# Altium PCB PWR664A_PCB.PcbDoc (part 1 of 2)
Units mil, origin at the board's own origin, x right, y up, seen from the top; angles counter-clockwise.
Board outline 3000 x 3000 mil, 4 copper layers (Top Layer, MidLayer1, MidLayer2, Bottom Layer), stack 31 mil thick; 122 components, 46 nets, 275 pads, 124 vias.
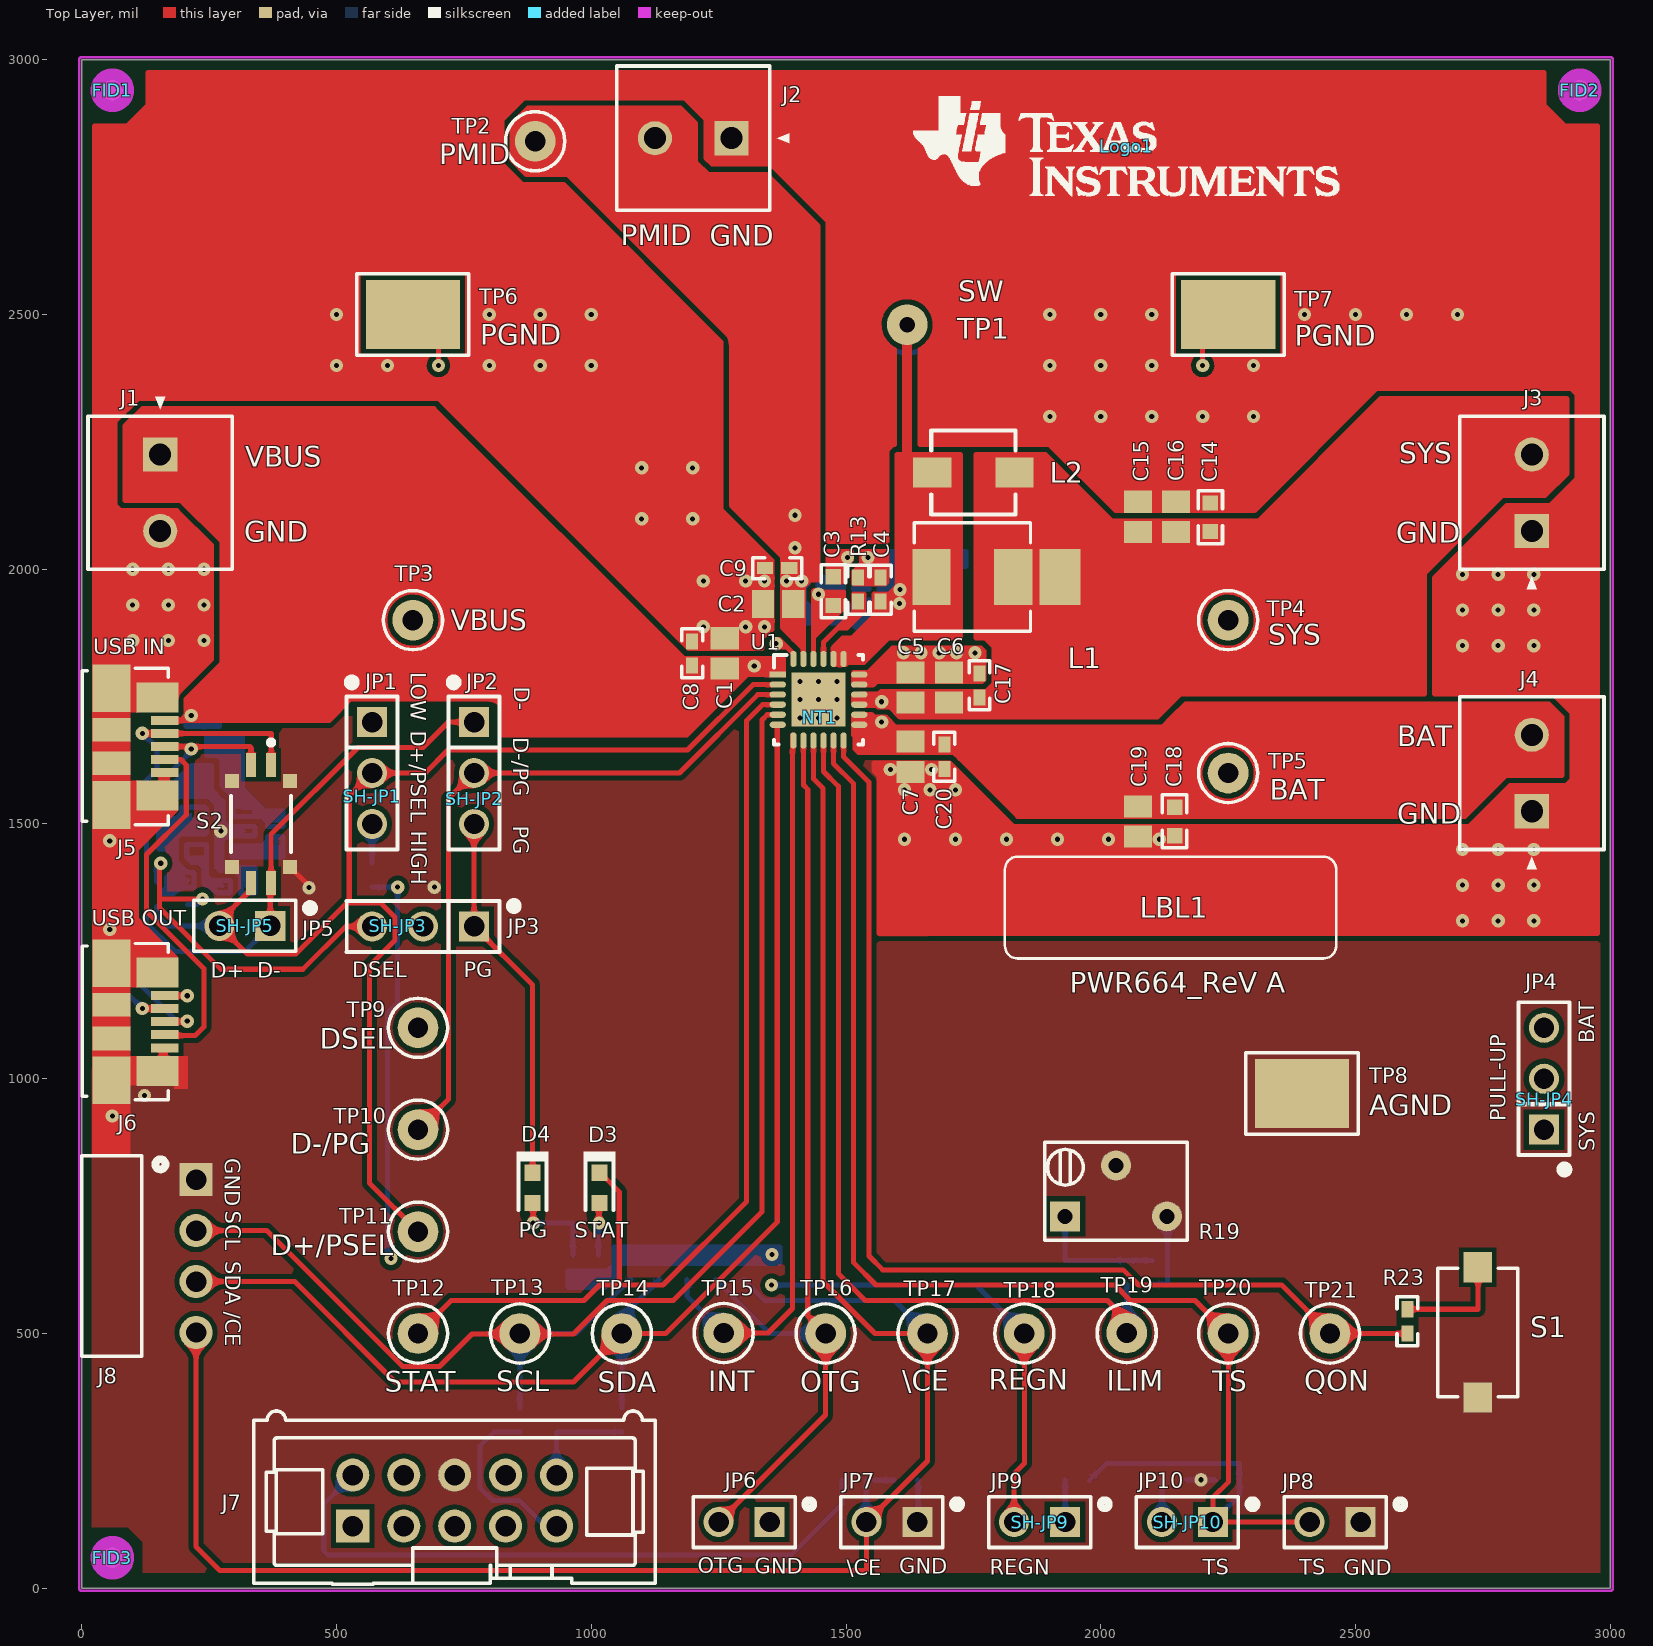
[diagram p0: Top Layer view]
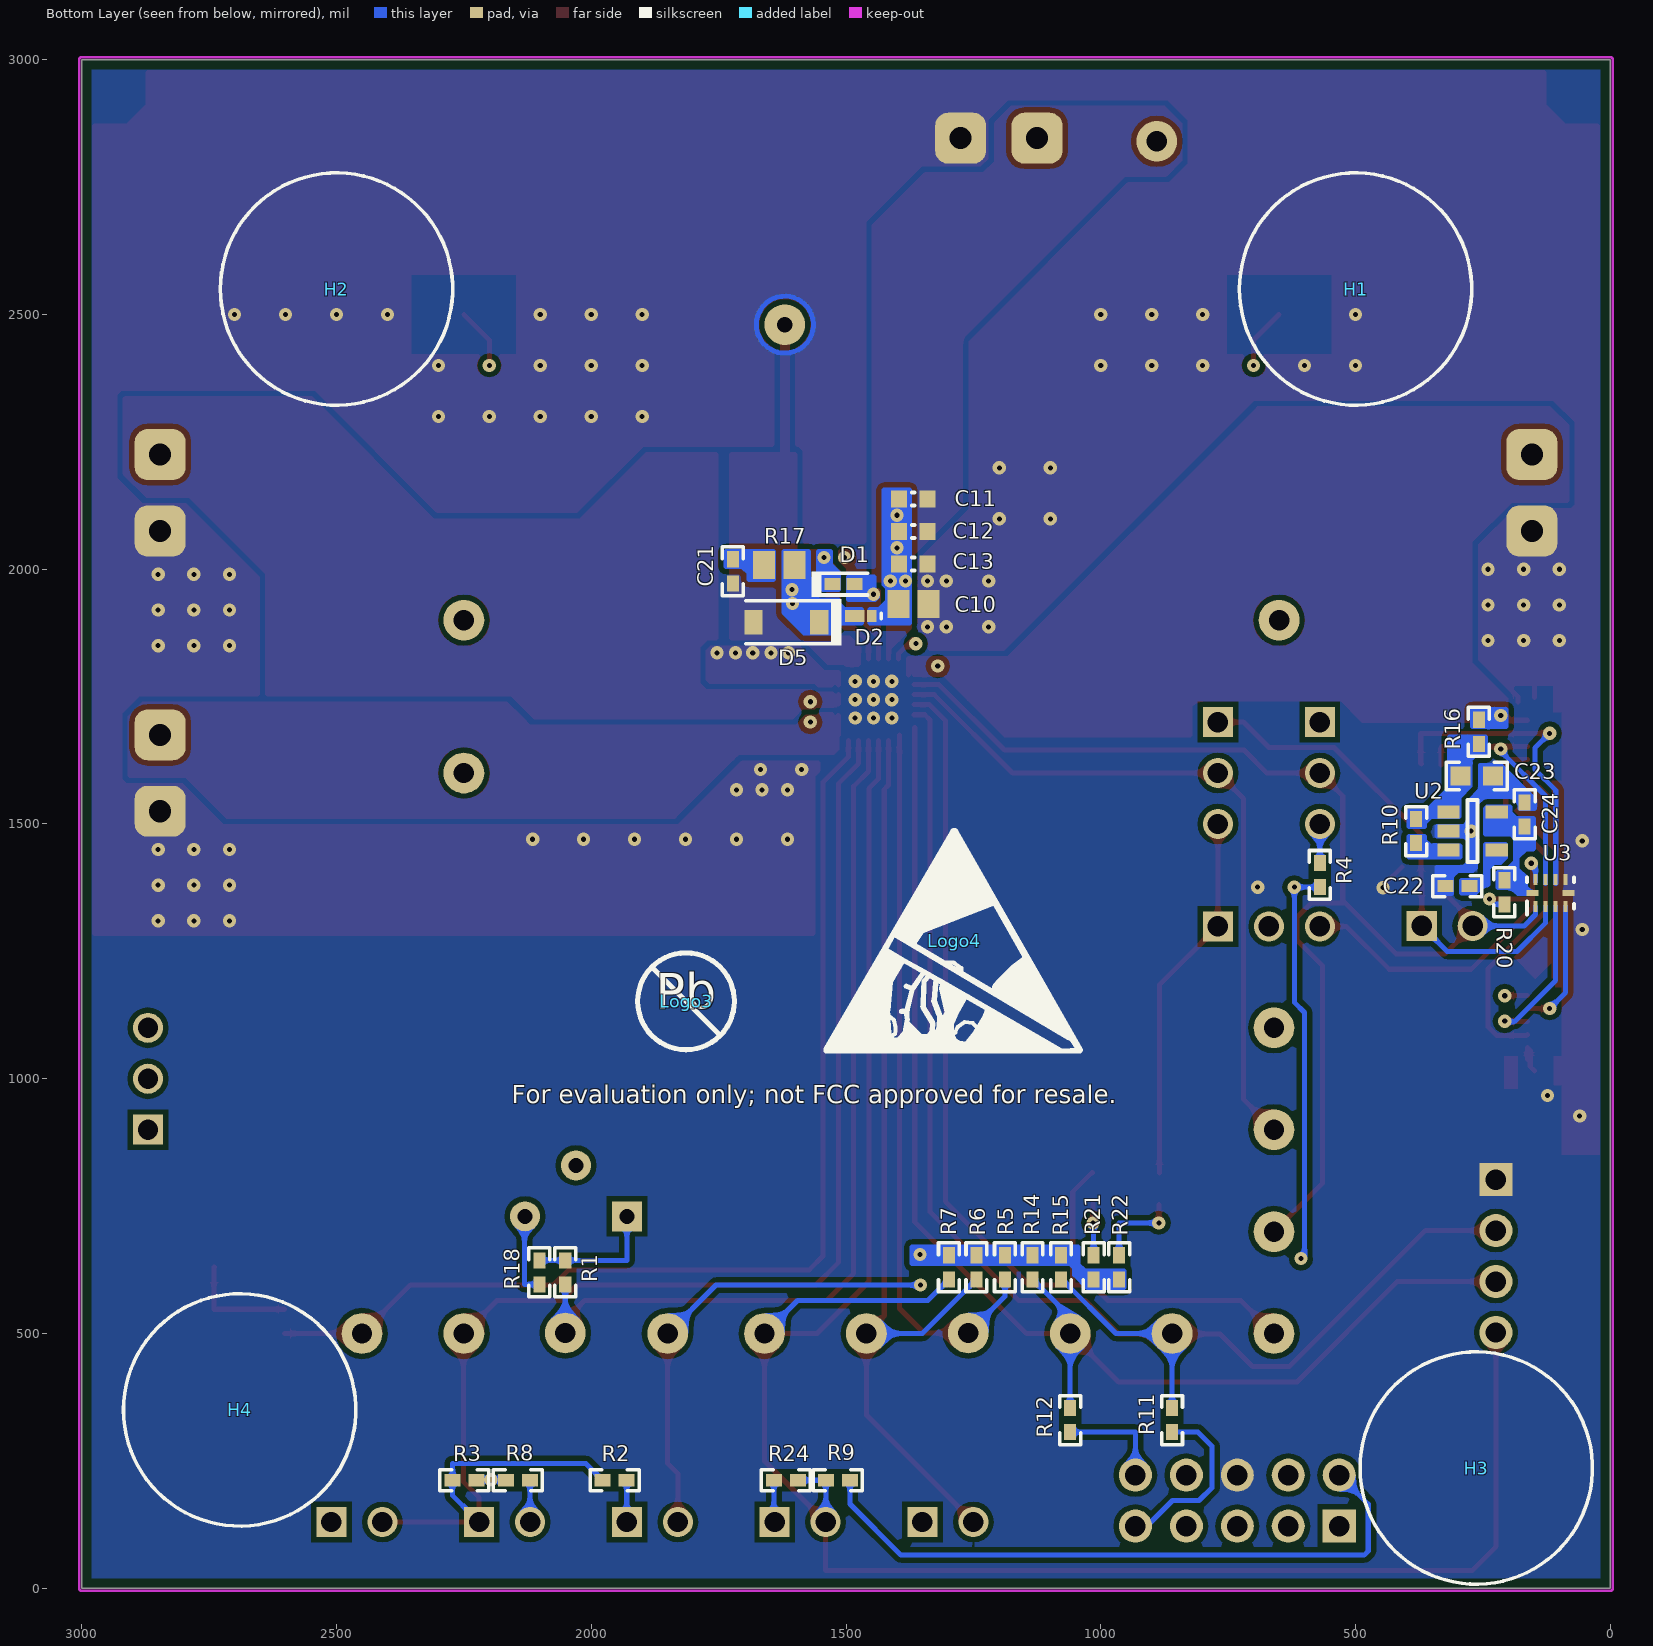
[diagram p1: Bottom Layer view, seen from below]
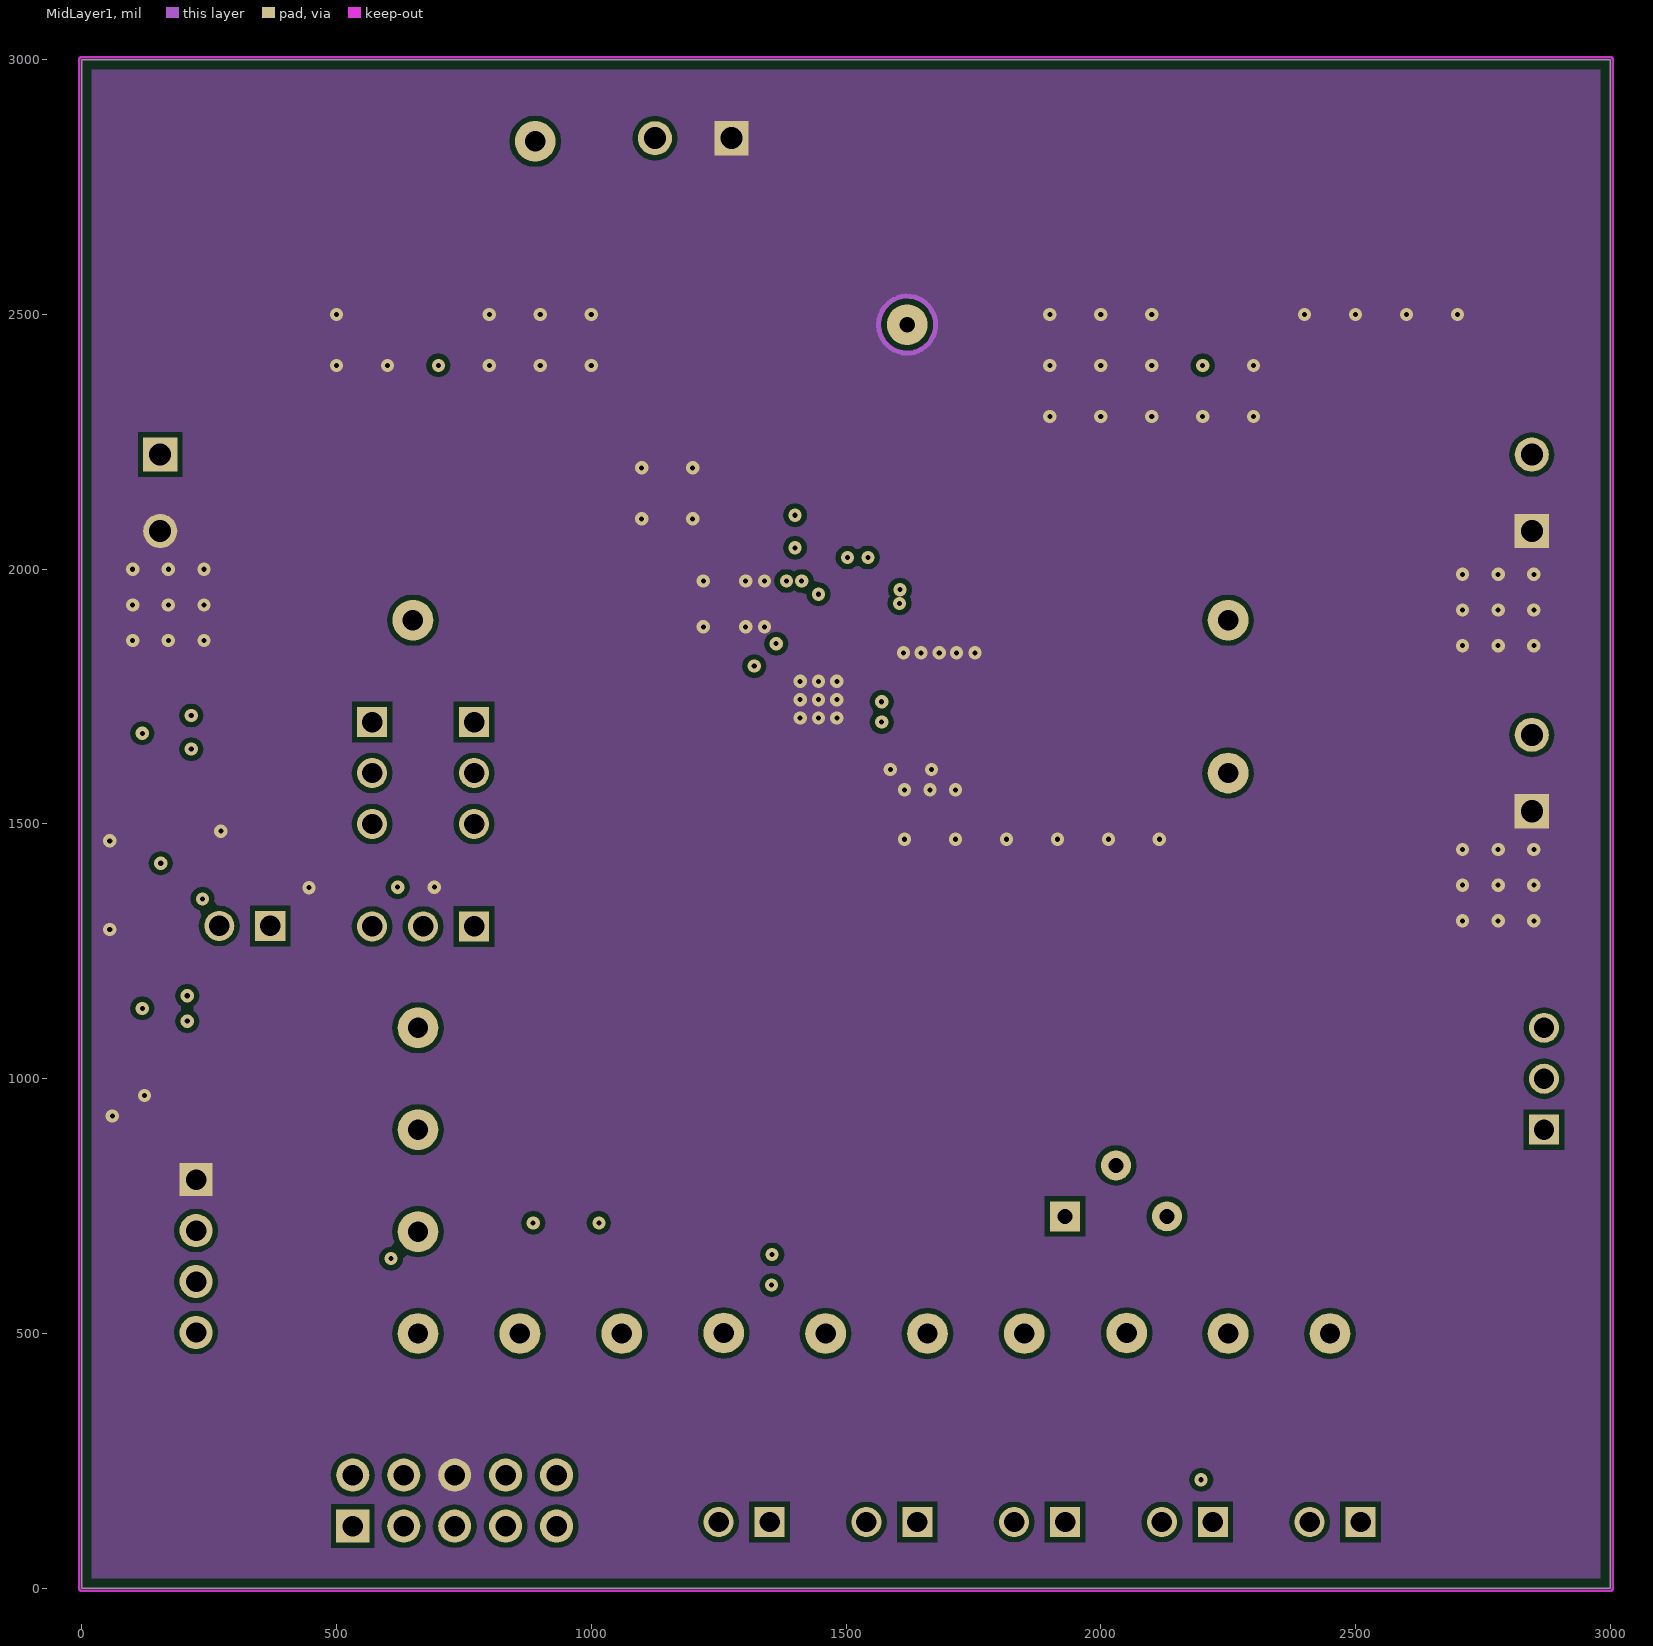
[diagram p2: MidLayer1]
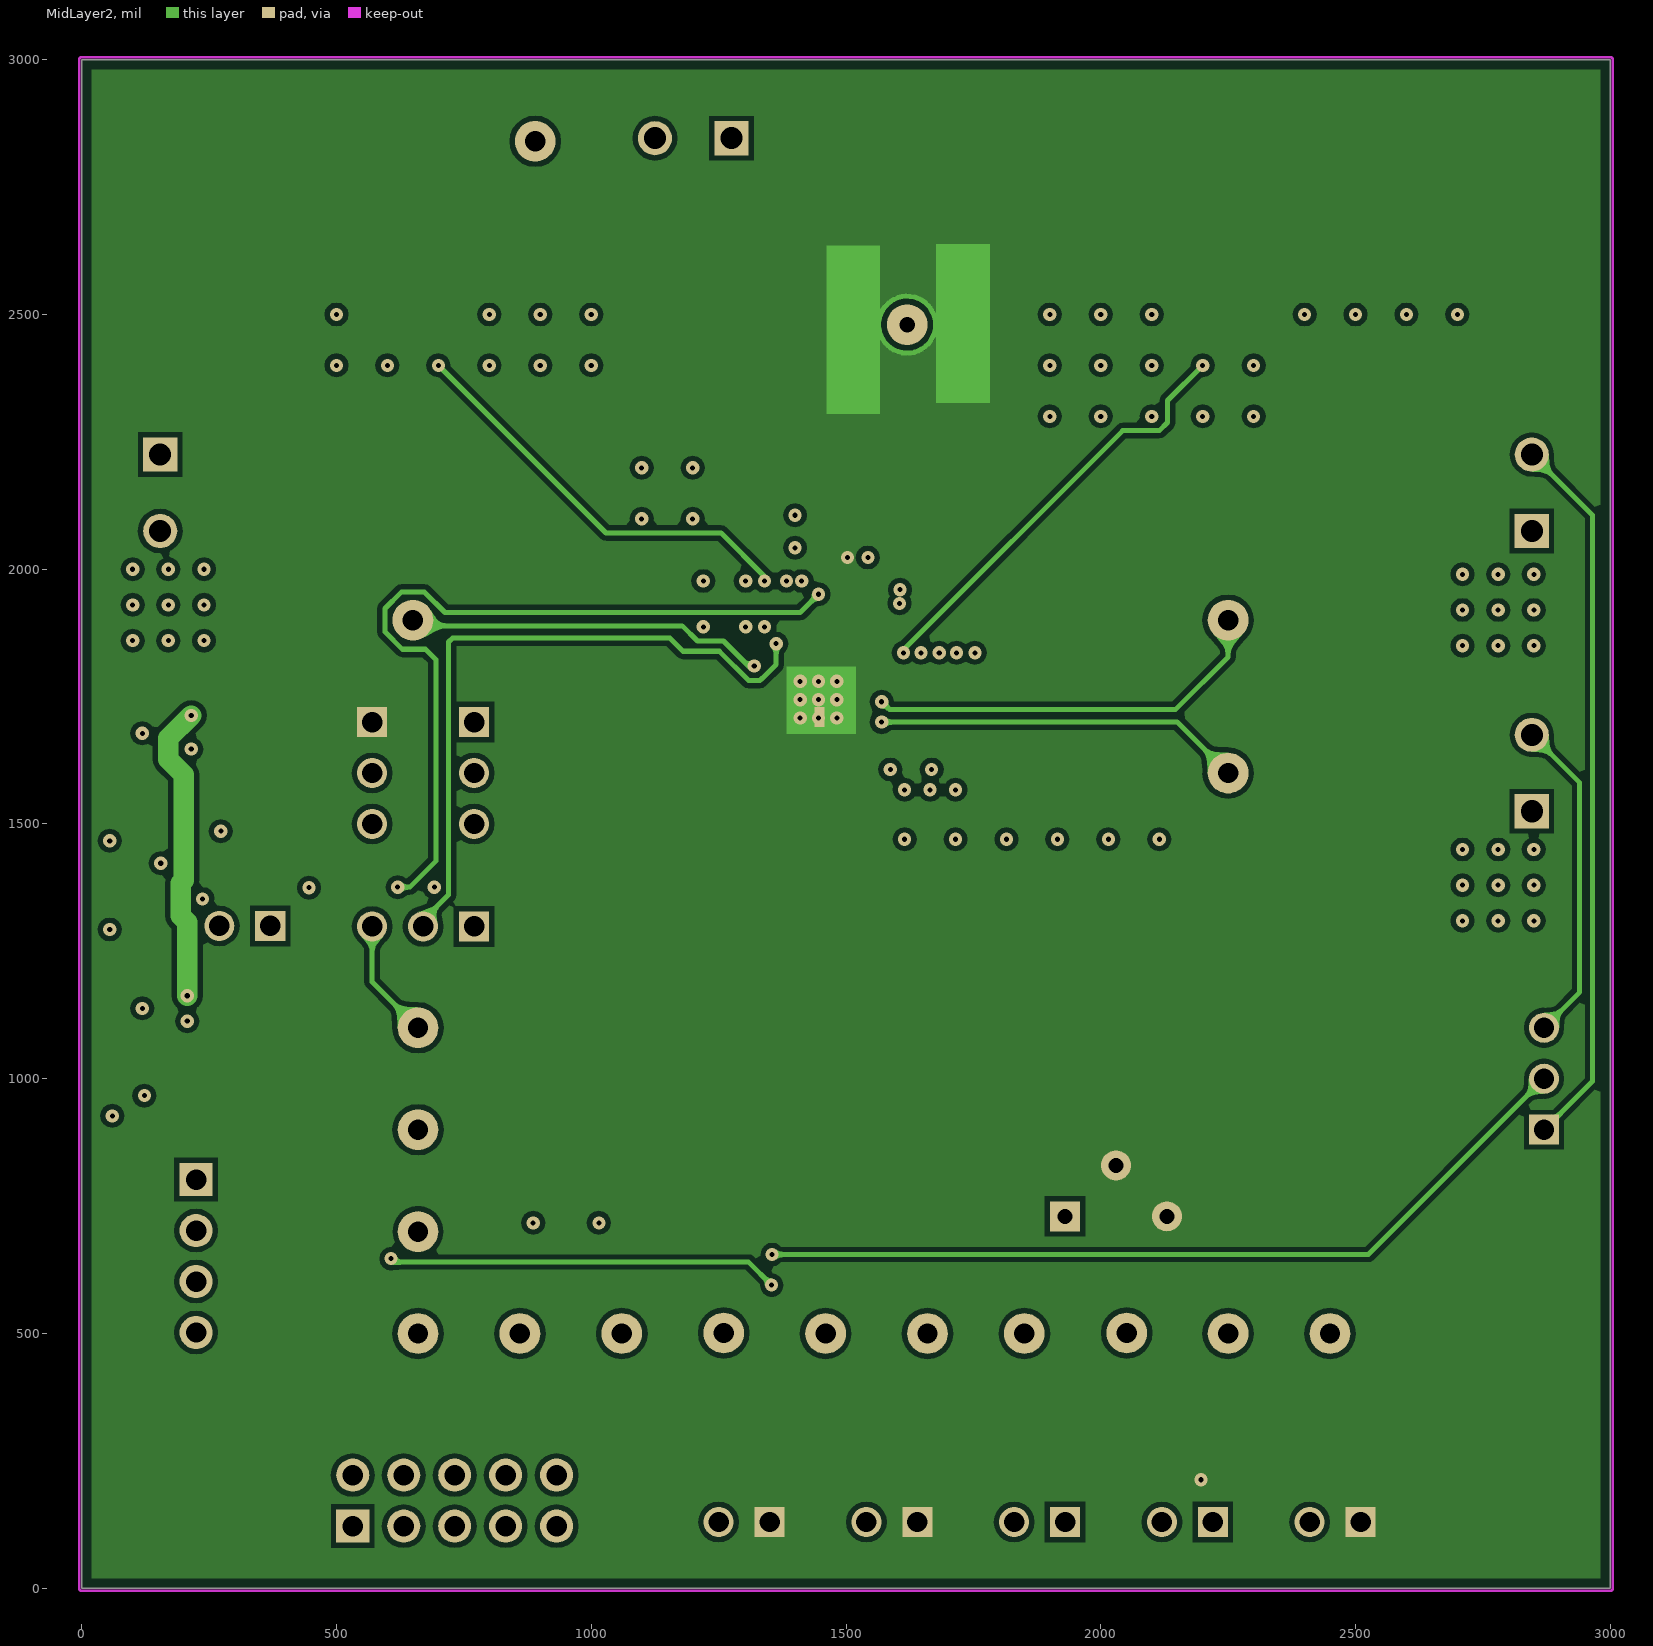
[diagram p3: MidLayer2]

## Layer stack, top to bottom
Top Solder: solder mask 0.4, Solder Resist, Dk 3.5
Top Layer: signal copper 2.8
Dielectric1: core 6.6, FR-4, Dk 4.8
MidLayer1: signal copper 2.8
Dielectric2: prepreg 6.6, FR-4, Dk 4.8
MidLayer2: signal copper 2.8
Dielectric3: core 6.6, FR-4, Dk 4.8
Bottom Layer: signal copper 2.8
Bottom Solder: solder mask 0.4, Solder Resist, Dk 3.5

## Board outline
0,0 3000,0 3000,3000 0,3000 0,0

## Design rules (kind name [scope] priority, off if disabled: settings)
AcuteAngle [All] p1: minimum=4.50000000000000E+0001 checktracksonly=FALSE
AssemblyTestPointUsage [All] p1: valid=2
Clearance Clearance_BoardEdge_MountingHoles [OnCopper and InComponentClass('Mounting Holes') vs IsKeepOut] p1: gap=10
Clearance Clearance_BoardEdge_Poly [OnCopper and InPoly vs IsKeepOut] p2: gap=10
Clearance Clearance_BoardEdge [OnCopper and Not InComponentClass('Logo') and not InComponentClass('FiducialMark') and not InRegion(1000,500,4000,800) and Not IsKeepout vs IsKeepOut] p3: gap=10
Clearance Clearance_Poly [InPolygon] p4: gap=10
Clearance [All] p5: gap=6
ComponentClearance ComponentClearance_Shunt [InComponentClass('Header') vs InComponentClass('Shunt')] p1: gap=10 collisioncheckmode=3 verticalgap=10 showdistances=FALSE
ComponentClearance ComponentClearance_Logo [InComponentClass('Logo')] p2: gap=10 collisioncheckmode=3 verticalgap=10 showdistances=FALSE
ComponentClearance ComponentClearance_ScrewToNut [(HasFootprint('NY PMS 440 0025 PH')) vs (HasFootprint('Keystone_1902C'))] p3: gap=10 collisioncheckmode=3 verticalgap=10 showdistances=FALSE
ComponentClearance ComponentClearance_MountingHoles [InComponentClass('Mounting Holes')] p4: gap=10 collisioncheckmode=3 verticalgap=100000 showdistances=FALSE
ComponentClearance ComponentClearance_SmallPassives [HasFootprint('0201*') or HasFootprint('0402*') or HasFootprint('0508') or HasFootprint('0603*') or HasFootprint('0612') or HasFootprint('0805*') or HasFootprint('0815*') or HasFootprint('0830*') or HasFootprint('1206*') or HasFootprint('1210*') or HasFootprint('1808*') or HasFootprint('1812*') or HasFootprint('1825*') or HasFootprint('2010*') or HasFootprint('2220*') or HasFootprint('2225*') or HasFootprint('2512*') or HasFootprint('2728*') or HasFootprint('3518*') vs HasFootprint('0201*') or HasFootprint('0402*') or HasFootprint('0508') or HasFootprint('0603*') or HasFootprint('0612') or HasFootprint('0805*') or HasFootprint('0815*') or HasFootprint('0830*') or HasFootprint('1206*') or HasFootprint('1210*') or HasFootprint('1808*') or HasFootprint('1812*') or HasFootprint('1825*') or HasFootprint('2010*') or HasFootprint('2220*') or HasFootprint('2225*') or HasFootprint('2512*') or HasFootprint('2728*') or HasFootprint('3518*')] p5: gap=10 collisioncheckmode=3 verticalgap=10 showdistances=FALSE
ComponentClearance ComponentClearance_THtoSMT [IsThruComponent vs IsSMTComponent] p6: gap=10 collisioncheckmode=3 verticalgap=10 showdistances=FALSE
ComponentClearance ComponentClearance_THtoTH [IsThruComponent vs IsThruComponent] p7: gap=10 collisioncheckmode=3 verticalgap=10 showdistances=FALSE
ComponentClearance [All] p8: gap=0 collisioncheckmode=3 verticalgap=0 showdistances=FALSE
DiffPairsRouting [All] p1: maxlimit=100 minlimit=10 mostfreqgap=10 toplayer_minwidth=15 toplayer_maxwidth=15 toplayer_prefwidth=15 midlayer1_minwidth=15 midlayer1_maxwidth=15 midlayer1_prefwidth=15 midlayer2_minwidth=15 midlayer2_maxwidth=15 midlayer2_prefwidth=15 bottomlayer_minwidth=15 bottomlayer_maxwidth=15 bottomlayer_prefwidth=15 maxuncoupledlength=1000
FabricationTestPointUsage TestPointUsage [All] p1: valid=2 allowmultiple=FALSE
FabricationTestpoint Testpoint [All] p1: side=3 testpointundercomponent=TRUE minsize=40 maxsize=100 preferedsize=60 minholesize=0 maxholesize=40 preferedholesize=32 testpointgrid=1 allowsidetop=TRUE allowsidebottom=TRUE usegrid=TRUE gridtolerance=0.01
FanoutControl Fanout_LCC [IsLCC] p1: bgadir=Out bgaviamode=Centered fanoutstyle=Auto fanoutdirection=Alternating viagrid=1 // Fanout_LCC (Default Rule)
FanoutControl Fanout_BGA [IsBGA] p2: bgadir=Out bgaviamode=Centered fanoutstyle=Auto fanoutdirection=Alternating viagrid=1 // Fanout_BGA (Default Rule)
FanoutControl Fanout_Default [All] p4: bgadir=Out bgaviamode=Centered fanoutstyle=Auto fanoutdirection=Alternating viagrid=1 // Fanout_Default (Default Rule)
FanoutControl Fanout_Small [(CompPinCount < 5)] p5: bgadir=Out bgaviamode=Centered fanoutstyle=Auto fanoutdirection=OutThenIn viagrid=1 // Fanout_Small (Default Rule)
HoleSize [All] p1: absolutevalues=TRUE maxlimit=500 minlimit=8 maxpercent=80.000 minpercent=20.000
MinimumAnnularRing MinimumAnnularRing_ThermalPadVias [IsVia and InAnyComponent] p1: minimumring=4
MinimumAnnularRing [All] p2: minimumring=6
MinimumSolderMaskSliver MinimumSolderMaskSliver_Logo [InComponentClass('Logo') vs InComponentClass('Logo')] p1: minsoldermaskwidth=0.7
MinimumSolderMaskSliver [All] p2: minsoldermaskwidth=3.94
PlaneClearance [All] p1: clearance=10
PlaneConnect [All] p1: planeconnectstyle=NoConnect reliefexpansion=10 reliefentries=4 reliefconductorwidth=10 reliefairgap=10
PolygonConnect [All] p1: connectstyle=Direct reliefconductorwidth=10 reliefentries=4 polygonreliefangle="90 Angle" airgapwidth=10
RoutingCorners [All] p1: cornerstyle=45-Degree minsetback=10 maxsetback=100
RoutingVias ThermalPadVias [IsVia and InAnyComponent] p1: holewidth=10 width=26 viastyle="Through Hole" minholewidth=6 minwidth=20 maxholewidth=100 maxwidth=200
RoutingVias [All] p2: holewidth=10 width=26 viastyle="Through Hole" minholewidth=6 minwidth=8 maxholewidth=200 maxwidth=300
SMDToCorner [All] p1: distance=0
SilkToSilkClearance [All] p1: silktosilkclearance=3
SilkToSolderMaskClearance SilkscreenOverComponentPads [IsPad] p1: minsilkscreentomaskgap=3 clearancetoexposedcopper=TRUE
SolderMaskExpansion [All] p1: expansion=0
UnpouredPolygon [All] p1: allowunpoured=FALSE
Width [All] p1: maxlimit=100 minlimit=5 preferedwidth=10 checkconnectedcopper=TRUE
13 further rules are at their usual default settings.

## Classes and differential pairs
component class Label: LBL1
component class FiducialMark: FID1 FID2 FID3
component class PWR664RevA_Hardware_ANSI-B: FID1 FID2 FID3 H1 H2 H3 H4 LBL1 Logo1 Logo2 Logo3 Logo4 SH-JP1 SH-JP2 SH-JP3 SH-JP4 SH-JP5 SH-JP9 SH-JP10 ZZ1 ZZ2 ZZ3 ZZ4
component class Logo: Logo1
component class PWR664RevA_Schematic: C1 C2 C3 C4 C5 C6 C7 C8 C9 C10 C11 C12 C13 C14 C15 C16 C17 C18 C19 C20 C21 C22 C23 C24 D1 D2 D3 D4 D5 J1 J2 J3 J4 J5 J6 J7 J8 JP1 JP2 JP3 JP4 JP5 JP6 JP7 JP8 JP9 JP10 L1 L2 NT1 R1 R2 R3 R4 R5 R6 R7 R8 R9 R10 R11 R12 R13 R14 R15 R16 R17 R18 R19 R20 R21 R22 R23 R24 S1 S2 TP2 TP3 TP4 TP5 TP6 TP7 TP8 TP9 TP10 TP11 TP12 TP13 TP14 TP15 TP16 TP17 TP18 TP19 TP20 TP21 U1 U2 U3
component class AssemblyNote: ZZ1 ZZ2 ZZ3 ZZ4
component class Shunt: SH-JP1 SH-JP2 SH-JP3 SH-JP4 SH-JP5 SH-JP9 SH-JP10

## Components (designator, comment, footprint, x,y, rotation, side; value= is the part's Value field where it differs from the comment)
C1 "GRM219R71E105KA88D" 0805L 1262,1835 r90 top
C2 "C2012X5R1E106K125AB" 0805L 1367,1932 r180 top
C3 "GRM188R61C475KAAJ" 0603_HV 1475,1957 r270 top
C4 "GRM155R71E473KA88D" 0402 1568,1960 r90 top
C5 "GRM21BR71A106KE51L" 0805L 1627,1768 r90 top
C6 "GRM21BR71A106KE51L" 0805L 1702,1768 r90 top
C7 "GRM21BR71A106KE51L" 0805L 1627,1632 r270 top
C8 "C1005C0G1E102J" 0402 1198,1835 r90 top
C9 "C1005C0G1E102J" 0402 1365,2002 r180 top
C10 "GRM21BR61E226ME44" 0805L 1367.5,1932 r180 bottom
C11 "GRM188R61E106MA73" 0603L 1368,2138 r180 bottom
C12 "GRM188R61E106MA73" 0603L 1368,2010 r180 bottom
C13 "GRM188R61E106MA73" 0603L 1368,2074 r180 bottom
C14 "C1608X7R1C104K" 0603_HV 2215,2102 r90 top
C15 "GRM21BR71A106KE51L" 0805L 2073,2103 r90 top
C16 "GRM21BR71A106KE51L" 0805L 2148,2103 r90 top
C17 "C1005C0G1E102J" 0402 1762,1772 r90 top
C18 "C1608X7R1C105K" 0603_HV 2145,1505 r270 top
C19 "GRM21BR71A106KE51L" 0805L 2073,1505 r270 top
C20 "C1005C0G1E102J" 0402 1693,1632 r270 top
C21 "C1005X7R1E103K" 0402 1722,1996 r270 bottom
C22 "C1005X7R1E103K" 0402 300,1378 r0 bottom
C23 "C1608X7R1E105K080AB" 0603 262,1594 r180 bottom
C24 "C1005X5R1A225K050BC" 0402 168,1519 r90 bottom
D1 "ZLLS350TA" SOD-523 1505,1971 r180 bottom
D2 "NSR10F20NXT5G" 152AD 1471,1908 r0 bottom
D3 "LTST-C190GKT" LED_LTST-C190 1016,786 r90 top
D4 "LTST-C190GKT" LED_LTST-C190 885,786 r90 top
D5 "B130LAW-7-F" SOD-123 1617,1896 r0 bottom
FID1 "Fiducial" Fiducial10-20 60,2940 r0 top
FID2 "Fiducial" Fiducial10-20 2940,2940 r0 top
FID3 "Fiducial" Fiducial10-20 60,60 r0 top
H1 "SJ-5303 (CLEAR)" Bumpon_SJ5003Transparent 500,2550 r180 bottom locked
H2 "SJ-5303 (CLEAR)" Bumpon_SJ5003Transparent 2500,2550 r180 bottom locked
H3 "SJ-5303 (CLEAR)" Bumpon_SJ5003Transparent 263,236 r180 bottom
H4 "SJ-5303 (CLEAR)" Bumpon_SJ5003Transparent 2690,350 r180 bottom locked
J1 "1727010" PhoenixConact_1727010 154,2150 r270 top locked
J2 "1727010" PhoenixConact_1727010 1200,2846 r180 top locked
J3 "1727010" PhoenixConact_1727010 2846,2150 r90 top locked
J4 "1727010" PhoenixConact_1727010 2846,1600 r90 top locked
J5 "0473460001" CONN_47346-0001 1,1652 r90 top locked
J6 "0473460001" CONN_47346-0001 1,1112 r90 top
J7 "N2510-6002-RB" CONN_2510-6002 732,172 r0 top
J8 "22-05-3041" CONN_22-05-3041 0,652 r270 top
JP1 "PEC03SAAN" CONN_PEC03SAAN 570,1600 r270 top
JP2 "PEC03SAAN" CONN_PEC03SAAN 770,1600 r270 top
JP3 "PEC03SAAN" CONN_PEC03SAAN 670,1299 r180 top
JP4 "PEC03SAAN" CONN_PEC03SAAN 2870,1000 r90 top
JP5 "PEC02SAAN" CONN_PEC02SAAN 320,1300 r180 top
JP6 "PEC02SAAN" CONN_PEC02SAAN 1300,130 r180 top
JP7 "PEC02SAAN" CONN_PEC02SAAN 1590,130 r180 top
JP8 "PEC02SAAN" CONN_PEC02SAAN 2460,130 r180 top
JP9 "PEC02SAAN" CONN_PEC02SAAN 1880,130 r180 top
JP10 "PEC02SAAN" CONN_PEC02SAAN 2170,130 r180 top
L1 "IHLP2020BZER1R0M11" IHLP-2020BZ 1748,1985 r0 top
L2 "SRP4012-1R5M" SRP4012 1750,2190 r0 top
LBL1 "Size: 0.65\" x 0.20 \"" Label_650x200 2137,1336 r0 top
Logo1 "Texas Instruments" TI_Stacked_Overlay_Small 2050,2830 r0 top
Logo2 "FCC disclaimer" FCC_disclaimer 4213,1712.99 r180 bottom
Logo3 "Pb-Free Symbol" Pb-Free_Overlay_Medium 1814,1152 r180 bottom
Logo4 "ESD Susceptible" ESD_Overlay_Large 1288,1271 r180 bottom
NT1 "Net-Tie" Net-Tie_20milWide_60milLong 1448,1750 r270 top net-tie
R1 "CRCW0402130RFKED" 0402 2051,620 r270 bottom
R2 "CRCW04025K23FKED" 0402 1954,212 r180 bottom
R3 "CRCW040230K1FKED" 0402 2249,212 r0 bottom
R4 "CRCW040210K0FKED" 0402 570,1400 r270 bottom
R5 "CRCW040210K0FKED" 0402 1188,630 r270 bottom
R6 "CRCW040210K0FKED" 0402 1244,630 r270 bottom
R7 "CRCW040210K0FKED" 0402 1298,630 r270 bottom
R8 "CRCW040210K0FKED" 0402 2144,212 r180 bottom
R9 "CRCW0402200RFKED" 0402 1516,212 r0 bottom
R10 "CRCW0402100KFKED" 0402 381,1486 r90 bottom
R11 "CRCW0402200RFKED" 0402 860,330 r270 bottom
R12 "CRCW0402200RFKED" 0402 1060,330 r90 bottom
R13 "CRCW04020000Z0ED" 0402 1524,1960 r90 top
R14 "CRCW040210K0FKED" 0402 1078,630 r270 bottom
R15 "CRCW040210K0FKED" 0402 1134,630 r270 bottom
R16 "CRCW04020000Z0ED" 0402 258,1681 r270 bottom
R17 "CRCW08051R00FKEA" 0805L 1631,2008 r180 bottom
R18 "CRCW0402768RFKED" 0402 2102,620 r90 bottom
R19 "3266W-1-103LF" TRIM_3266W 1930,730 r90 top
R20 "CRCW040210K0FKED" 0402 208,1366 r270 bottom
R21 "CRCW04022K21FKED" 0402 1014,630 r270 bottom
R22 "CRCW04022K21FKED" 0402 964,630 r270 bottom
R23 "CRCW04024K70JNED" 0402 2602,524 r270 top
R24 "CRCW040210K0FKED" 0402 1618,212 r180 bottom
S1 "KSR221GLFS" KSR 2740,502 r270 top
S2 "CVS-02TB" SW_CVS-02B 352,1500 r270 top
SH-JP1 "969102-0000-DA" SNT-100-BK-G 569,1554 r90 top
SH-JP2 "969102-0000-DA" SNT-100-BK-G 770,1550 r90 top
SH-JP3 "969102-0000-DA" SNT-100-BK-G 620,1300 r180 top
SH-JP4 "969102-0000-DA" SNT-100-BK-G 2870,960 r90 top
SH-JP5 "969102-0000-DA" SNT-100-BK-G 320,1300 r180 top
SH-JP9 "969102-0000-DA" SNT-100-BK-G 1880,130 r180 top
SH-JP10 "969102-0000-DA" SNT-100-BK-G 2170,130 r180 top
TP2 "5000" Keystone5000 890,2840 r0 top
TP3 "5000" Keystone5000 650,1900 r0 top
TP4 "5003" Keystone5003 2250,1900 r0 top
TP5 "5004" Keystone5004 2250,1600 r0 top
TP6 "5016" Testpoint_Keystone_Compact 650,2500 r0 top
TP7 "5016" Testpoint_Keystone_Compact 2250,2500 r0 top
TP8 "5016" Testpoint_Keystone_Compact 2395,971 r0 top
TP9 "5002" Keystone5002 660,1100 r90 top
TP10 "5002" Keystone5002 660,900 r90 top
TP11 "5002" Keystone5002 660,700 r90 top
TP12 "5002" Keystone5002 660,500 r90 top
TP13 "5002" Keystone5002 860,500 r90 top
TP14 "5002" Keystone5002 1060,500 r90 top
TP15 "5002" Keystone5002 1260,501 r90 top
TP16 "5002" Keystone5002 1460,500 r90 top
TP17 "5002" Keystone5002 1660,500 r90 top
TP18 "5003" Keystone5003 1850,500 r0 top
TP19 "5002" Keystone5002 2051,501 r90 top
TP20 "5002" Keystone5002 2250,500 r90 top
TP21 "5002" Keystone5002 2450,500 r90 top
U1 "BQ25890RTWR" RGE0024H 1446,1744 r0 top locked
U2 "LP2985AIM5-3.3/NOPB" DBV0005A_N 270,1486 r180 bottom
U3 "TS3USB221ARSER" RSE0010A 117,1364.86 r90 bottom
ZZ1 "This Assembly Note is for PCB labels only" AssemblyNoteLabel 171,3916 r0 top
ZZ2 "These assemblies are ESD sensitive, ESD precautions shall be observed." AssemblyNote 171,3807.11 r0 top
ZZ3 "These assemblies must be clean and free from flux and all contaminants. Use of no clean flux is not acceptable." AssemblyNote 171,3718.56 r0 top
ZZ4 "These assemblies must comply with workmanship standards IPC-A-610 Class 2, unless otherwise specified." AssemblyNote 171,3630 r0 top

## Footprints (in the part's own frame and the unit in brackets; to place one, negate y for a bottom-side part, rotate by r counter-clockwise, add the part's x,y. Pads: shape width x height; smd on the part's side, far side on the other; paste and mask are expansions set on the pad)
152AD [mm] "ON SEMICONDUCTOR, DSN2, 1.4x0.6, 0.75P"
  rect 0.47x0.6 smd: 1(-0.54,0)
  rect 0.95x0.6 smd: 2(0.3,0)
  silkscreen extent -1.02,-0.15 -1.02,0.15, body extent -0.7,-0.3 0.7,0.3, height 0.32
0402 [mm] "0402 from SM-752 data"
  rect 0.8x0.6 smd: 1(-0.6,0) 2(0.6,0)
  silkscreen extent -1.22,-0.52 1.22,0.52, body extent -0.55,-0.3 0.55,0.3, height 0.6
0603 [mm] "0603 from SM-752 data"
  rect 1x0.95 smd: 1(-0.8,0) 2(0.8,0)
  silkscreen extent -1.52,-0.69 1.52,0.69, body extent -0.87,-0.47 0.87,0.47, height 0.85
0603_HV [mil] "Ernesto recommended land pattern.  26 mil between pads."
  rect 30x30 smd: 1(-28,0) 2(28,0)
  silkscreen extent -52,-24 52,24, body extent -34,-19 34,19, height 33
0603L [mm] "0603 from SM-752 data"
  rect 0.8x0.85 smd: 1(-0.7,0) 2(0.7,0)
  silkscreen extent -0.07,-0.33 0.07,0.33, body extent -0.87,-0.47 0.87,0.47, height 0.85
0805L [mm] "0805 from SM-752 data"
  rect 1.1x1.4 smd: 1(-0.75,0) 2(0.75,0)
  body extent -1.1,-0.72 1.1,0.72, height 1.1
AssemblyNote [mil] "Assembly Note"
AssemblyNoteLabel [mil] "Assembly Note for PCB Labels"
Bumpon_SJ5003Transparent [mil] "3M Hemispherical Bumpon transparent"
  round 1 on Mech4: 0(0,0)
  silkscreen extent -228,-228 228,228, body extent -217,-218 219,218, height 197
CONN_22-05-3041 [mm] "MOLEX"
  rect 1.65x1.65 hole 1.02: 1(-3.81,5.7)
  round 1.65 hole 1.02: 2(-1.27,5.7) 3(1.27,5.7) 4(3.81,5.7)
  silkscreen extent -5,0 5,4.18, body extent -5,-6.91 5,6.02, height 6.37
CONN_2510-6002 [mm] "3M 2500 series TS-0770-L December 15, 2011"
  rect 1.65x1.65 hole 1.016 mask+0: 1(-5.08,-1.27)
  round 1.65 hole 1.016 mask+0: 2(-5.08,1.27) 3(-2.54,-1.27) 4(-2.54,1.27) 5(0,-1.27) 6(0,1.27) 7(2.54,-1.27) 8(2.54,1.27) 9(5.08,-1.27) 10(5.08,1.27)
  silkscreen extent -10.01,-4.17 10.01,4.47, body extent -10.01,-4.11 10.01,4.52, height 9.92
CONN_47346-0001 [mm] "MOLEX"
  rect 0.45x1.38 smd mask+0.043: 1(1.3,-4.105) 2(0.65,-4.105) 3(0,-4.105) 4(-0.65,-4.105) 5(-1.3,-4.105)
  rect 1.5x2.1 smd mask+0.043: 6(-2.45,-3.755) 11(2.45,-3.75)
  rect 2.375x1.9 smd mask+0.043: 7(-2.912,-1.45) 10(2.912,-1.45)
  rect 1.175x1.9 smd mask+0.043: 8(-0.837,-1.45) 9(0.837,-1.45)
  silkscreen extent -3.9,-4.28 3.9,0, body extent -3.99,-4.43 3.99,1, height 2.72
CONN_PEC02SAAN [mm] "SULLINS"
  rect 1.5x1.5 hole 1.016: 1(-1.27,0)
  round 1.5 hole 1.016: 2(1.27,0)
  silkscreen extent -3.45,-1.27 2.54,1.27, body extent -2.54,-1.27 2.54,1.27, height 8.38
CONN_PEC03SAAN [mm] "SULLINS"
  rect 1.5x1.5 hole 1.016: 1(-2.54,0)
  round 1.5 hole 1.016: 2(0,0) 3(2.54,0)
  silkscreen extent -4.72,-1.27 3.81,1.27, body extent -3.84,-1.3 3.84,1.3, height 8.38
DBV0005A_N [mm] "SOT23, 5-Leads, Body 2.9x1.6mm, Pitch 0.95mm, Lead Span 2.8mm, IPC Medium Density"
  rect 1.1x0.65 smd: 1(-1.2,0.95) 2(-1.2,0) 3(-1.2,-0.95) 4(1.2,-0.95) 5(1.2,0.95)
  silkscreen extent -0.25,-1.55 0.25,1.55, body extent -1.42,-1.46 1.42,1.46, height 1.08
ESD_Overlay_Large [mil]
  silkscreen extent -254,-219 250,219
FCC_disclaimer [mil]
Fiducial10-20 [mm]
  round 1 smd paste-0.5 mask+0.5: 1(0,0)
  Top Layer keep-out circle w1.178: c0,0 r0.5
IHLP-2020BZ [mm] "Vishay Dale recommended land pattern.  Document 34261 rev 12-Sept-13"
  rect 1.915x2.79 smd: 1(-2.037,0) 2(2.037,0)
  silkscreen extent -2.9,-2.7 2.9,2.7, body extent -2.87,-2.72 2.87,2.72, height 2
Keystone5000 [mil] "For Keystone 500x miniature loop terminals"
  round 80 hole 40: 1(0,0)
  silkscreen extent -58,-58 58,58, body extent -49,-49 49,49, height 182
Keystone5002 [mil] "For Keystone 500x miniature loop terminals"
  round 80 hole 40: 1(0,0)
  silkscreen extent -58,-58 58,58, body extent -49,-49 49,49, height 182
Keystone5003 [mil] "For Keystone 500x miniature loop terminals"
  round 80 hole 40: 1(0,0)
  silkscreen extent -58,-58 58,58, body extent -49,-49 49,49, height 182
Keystone5004 [mil] "For Keystone 500x miniature loop terminals"
  round 80 hole 40: 1(0,0)
  silkscreen extent -58,-58 58,58, body extent -49,-49 49,49, height 182
KSR [mm] "C&K Components SPST switch"
  rect 1.5x1.4 smd: 1(-3.25,0) 2(3.25,0)
  silkscreen extent -3.2,-2 3.2,2, body extent -3,-1.9 3,1.9, height 2.65
Label_650x200 [mil] "Thermal Transfer Label"
  silkscreen extent -325,-100 325,100, body extent -326,-101 326,101, height 1
LED_LTST-C190 [mm] "Lite-On"
  rect 0.8x0.8 smd: 1(-0.75,0) 2(0.75,0)
  silkscreen extent -1.1,-0.8 1.8,0.8, body extent -0.85,-0.45 0.85,0.45, height 0.9
Net-Tie_20milWide_60milLong [mil] "20mil net tie, no solder mask opening, no solder paste"
  rect 20x20 on Mid2 paste-10 mask-10: 1(30,0) 2(50,0)
Pb-Free_Overlay_Medium [mil]
  silkscreen extent -95,-95 95,95
PhoenixConact_1727010 [mm]
  rect 1.7x1.7 hole 1.1: 1(-1.905,0)
  round 1.7 hole 1.1: 2(1.905,0)
  silkscreen extent -4.8,-3.6 3.81,3.6, body extent -3.81,-3.6 3.81,3.7, height 8.52
RGE0024H [mil] "QFN, 24-Leads, Body 4x4mm, Pitch 0.5mm, Thermal Pad 2.7x2.7mm, TI Recommended"
  rect 32x12 smd: 1(-80,49.21)
  oval 32x12 smd: 2(-80,29.53) 3(-80,9.84) 4(-80,-9.84) 5(-80,-29.53) 6(-80,-49.21) 13(80,-49.21) 14(80,-29.53) 15(80,-9.84) 16(80,9.84) 17(80,29.53) 18(80,49.21)
  oval 12x32 smd: 7(-49.21,-80) 8(-29.53,-80) 9(-9.84,-80) 10(9.84,-80) 11(29.53,-80) 12(49.21,-80) 19(49.21,80) 20(29.53,80) 21(9.84,80) 22(-9.84,80) 23(-29.53,80) 24(-49.21,80)
  rect 106x106 smd paste-53.15: 25(0,0)
  silkscreen extent -88,-88 88,88, body extent -82,-82 82,82, height 40
RSE0010A [mm] "QFN, 10-Leads, Body 1.5x2mm, Pitch 0.5mm, TI Recommended"
  rect 0.55x0.2 smd: 1(-0.675,0.75) 2(-0.675,0.25) 3(-0.675,-0.25) 4(-0.675,-0.75) 6(0.675,-0.75) 7(0.675,-0.25) 8(0.675,0.25) 9(0.675,0.75)
  rect 0.3x0.6 smd: 5(0,-0.9) 10(0,0.9)
  silkscreen extent -1.07,-1.17 0.77,1.18, body extent -0.77,-1.02 0.78,1.03, height 0.61
SNT-100-BK-G [mil] "Samtec STEP model"
  round 1 on Mech3: 0(0,0)
  body extent -100,-50 100,50, height 344
SOD-123 [mm] "On Semi recommended land pattern"
  rect 0.915x1.22 smd: 1(-1.637,0) 2(1.637,0)
  silkscreen extent -2.74,-1.17 2.03,1.17, body extent -1.93,-0.9 1.93,0.9, height 1.35
SOD-523 [mm] "NXP Semiconductor recommended land pattern, nominal STEP model"
  rect 0.8x0.6 smd paste-0.05: 1(-0.55,0) 2(0.55,0)
  silkscreen extent -1.6,-0.63 1.2,0.64, body extent -0.8,-0.4 0.8,0.4, height 0.72
SRP4012 [mm] "BOURNS"
  rect 1.9x1.5 smd: 1(-2.05,0) 2(2.05,0)
  silkscreen extent -2.1,-2.1 2.1,2.1, body extent -2.1,-2.1 2.1,2.1, height 1.2
SW_CVS-02B [mm] "Copal Electronics"
  rect 1.2x0.5 smd: 1(-2.95,0.5) 2(-2.95,-0.5) 3(2.95,-0.5) 4(2.95,0.5)
  rect 0.7x0.7 smd: M1(-2.15,1.45) M2(-2.15,-1.45) M3(2.15,-1.45) M4(2.15,1.45)
  silkscreen extent -4.19,-1.5 1.4,1.5, body extent -2.15,-1.5 2.15,1.5, height 1.45
Testpoint_Keystone_Compact [mil] "Compact SMT test point"
  rect 185x135 smd: 1(0,0)
  silkscreen extent -110,-80 110,80, body extent -75,-56 75,56, height 91
TI_Stacked_Overlay_Small [mil]
  silkscreen extent -418,-98 418,98
TRIM_3266W [mm] "Bourns 3266W series REV 08/10"
  rect 1.5x1.5 hole 0.75: 1(0,0)
  round 1.5 hole 0.75: 2(2.54,-2.54) 3(0,-5.08)
  silkscreen extent -1.2,-6.09 3.68,1.01, body extent -1.2,-6.09 3.68,1.01, height 8.45

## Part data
C1: "CAP, CERM, 1 µF, 25 V, +/- 10%, X7R, 0805"
C2: "CAP, CERM, 10uF, 25V, +/-10%, X5R, 0805"
C3: "CAP, CERM, 4.7uF, 16V, +/-10%, X5R, 0603"
C4: "CAP, CERM, 0.047uF, 25V, +/-10%, X7R, 0402"
C5 C6 C7 C15 C16 C19: "CAP, CERM, 10 µF, 10 V, +/- 10%, X7R, 0805"
C8 C9 C17 C20: "CAP, CERM, 1000pF, 25V, +/-5%, C0G/NP0, 0402"
C10: "CAP, CERM, 22 µF, 25 V, +/- 20%, X5R, 0805"
C11 C12 C13: "CAP, CERM, 10uF, 25V, +/-20%, X5R, 0603"
C14: "CAP, CERM, 0.1uF, 16V, +/-10%, X7R, 0603"
C18: "CAP, CERM, 1uF, 16V, +/-10%, X7R, 0603"
C21 C22: "CAP, CERM, 0.01uF, 25V, +/-10%, X7R, 0402"
C23: "CAP, CERM, 1uF, 25V, +/-10%, X7R, 0603"
C24: "CAP, CERM, 2.2uF, 10V, +/-10%, X5R, 0402"
D1: "Diode, Schottky, 40V, 0.38A, SOD-523"
D2: "Diode, Schottky, 20 V, 1 A, 1.4x0.6x0.31mm"
D3 D4: "LED, Green, SMD"
D5: "Diode, Schottky, 30 V, 1 A, SOD-123"
FID1 FID2 FID3: "Fiducial mark.  There is nothing to buy or mount."
H1 H2 H3 H4: "Bumpon, Hemisphere, 0.44 X 0.20, Clear"
J1 J2 J3 J4: "Conn Term Block, 2POS, 3.81mm, TH"
J5 J6: "Connector, Receptacle, Micro-USB Type B, R/A, Bottom Mount SMT"
J7: "Header (shrouded), 100mil, 5x2, High-Temperature, Gold, TH"
J8: "Header, 100mil, 4x1, R/A, TH"
JP1 JP2 JP3 JP4: "Header, 100mil, 3x1, Tin plated, TH"
JP5 JP6 JP7 JP8 JP9 JP10: "Header, 100mil, 2x1, Tin plated, TH"
L1: "Inductor, Shielded Drum Core, Powdered Iron, 1uH, 7A, 0.0181 ohm, SMD"
L2: "Inductor, Flat Wire, Powdered Iron, 1.5 µH, 3 A, 0.05 ohm, SMD"
LBL1: library part THT-14-423-10, "Thermal Transfer Printable Labels, 0.650\" W x 0.200\" H - 10,000 per roll"
Logo1: library part TI_Logo, "Texas Instrument Corporate Signature"
Logo2: library part FCC_disclaimer, "FCC_disclaimer"
Logo3: library part Pb-Free
Logo4: library part ESD_Susceptible, "ESD Susceptible Symbol"
NT1: "Single point connection between nets."
R1: "RES, 130 ohm, 1%, 0.063W, 0402"
R2: "RES, 5.23k ohm, 1%, 0.063W, 0402"
R3: "RES, 30.1k ohm, 1%, 0.063W, 0402"
R4 R5 R6 R7 R8 R14 R15 R20 R24: "RES, 10.0k ohm, 1%, 0.063W, 0402"
R9 R11 R12: "RES, 200 ohm, 1%, 0.063W, 0402"
R10: "RES, 100k ohm, 1%, 0.063W, 0402"
R13 R16: "RES, 0 ohm, 5%, 0.063W, 0402"
R17: "RES, 1.00 ohm, 1%, 0.125W, 0805"
R18: "RES, 768 ohm, 1%, 0.063W, 0402"
R19: "Trimmer, 10k ohm, 0.25W, TH"
R21 R22: "RES, 2.21k ohm, 1%, 0.063W, 0402"
R23: "RES, 4.7k ohm, 5%, 0.063W, 0402"
S1: "Switch, Normally open, 2.3N force, 200k operations, SMD"
S2: "DIP Switch, SPST, 2Pos, Slide, SMT"
SH-JP1 SH-JP2 SH-JP3 SH-JP4 SH-JP5 SH-JP9 SH-JP10: "Shunt, 100mil, Gold plated, Black"
TP2 TP3: "Test Point, Miniature, Red, TH"
TP4 TP18: "Test Point, Miniature, Orange, TH"
TP5: "Test Point, Miniature, Yellow, TH"
TP6 TP7 TP8: "Test Point, Compact, SMT"
TP9 TP10 TP11 TP12 TP13 TP14 TP15 TP16 TP17 TP19 TP20 TP21: "Test Point, Miniature, White, TH"
U1: "I2C Controlled 5A Single Cell Charger with NVDC Power Path Management and MaxChargeTM High Voltage Adapter Support, RTW0024H"
U2: "Micropower 150 mA Low-Noise Ultra Low-Dropout Regulator in SOT-23 Package, DBV0005A"
U3: "ESD Protected,High-Speed USB 2.0 (480-Mbps) 1:2 Multiplexer / Demultiplexer Switch, 1:2 Mux / Demux, 6 ohm RON, 2.5 to 3.3V, -40 to 85 degC, 10-Pin UQFN (RSE), Green (RoHS & no Sb/Br)"
ZZ1: library part AssemblyNoteLabel
ZZ2 ZZ3 ZZ4: library part AssemblyNote

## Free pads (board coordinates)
  rrect50% 100x100 smd far side: 0(154,2075) 1(154,2225) 2(1125,2846) 3(1275,2846) 4(2846,2225) 5(2846,2075) 6(2846,1675) 7(2846,1525)
  round 80 hole 30: 0(1620,2480)
  rect 80x110 smd: 0(1920,1985)

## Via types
v1: diameter 26, hole 10, Top Layer to Bottom Layer, tented both sides, 115 vias
v2: diameter 26, hole 10, Top Layer to Bottom Layer, tented bottom, 9 vias

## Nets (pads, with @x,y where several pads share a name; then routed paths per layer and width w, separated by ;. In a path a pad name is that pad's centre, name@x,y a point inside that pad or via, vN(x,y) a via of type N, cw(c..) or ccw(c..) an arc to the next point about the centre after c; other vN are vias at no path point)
3.3V: C24.1 R20.1 U2.5 U3.10 | length 631.8
  Bottom Layer w10: U3.10@152.43,1364.86 U3.10@155.93,1364.86 ; C24.1@168,1495.38 150.38,1495.38 ; R20.1@208,1389.62 206.47,1389.62 192.45,1375.6 ; 150.38,1495.38 150.38,1510.38 151,1511 185.41,1511 197.13,1522.72 197.13,1532.84 241.87,1532.84 245,1529.72 245,1480 194,1480 186.1,1472.1 186.1,1425.9 207,1405 220,1405 220,1375.6 192.45,1375.6 ; 150.38,1495.38 150.38,1452.38 151.76,1451 166.6,1451 183,1434.6 183,1411.4 166.53,1394.93 166.53,1375.46 U3.10@155.93,1364.86 ; U3.10@155.93,1364.86 156.79,1364 180.85,1364 192.45,1375.6
\CE: J8.4 JP7.2 R7.2 R9.2 R24.2 TP17.1 U1.9 | length 4113.8
  Top Layer w10: J8.4@224.41,502 224.41,81.59 271,35 1540,35 JP7.2@1540,130 1660,250 TP17.1@1660,500 1557,500 1455,602 1455,1570 1436.16,1588.84 U1.9@1436.16,1664
  Bottom Layer w10: R7.2@1298,606.38 1339.38,565 1595,565 TP17.1@1660,500 ; JP7.2@1539.62,130.38 R9.2@1539.62,212 ; R9.2@1555.37,212 R24.2@1594.38,212
AGND: C3.1 JP1.1 JP6.1 JP7.1 JP8.1 NT1.2 R3.1 R8.1 R18.1 R19.2 R19.3 R24.1 S1.2 TP8.1 | length 910.5
  Top Layer w10: C3.1@1485,1975 1495,1975 ; 1465.1,2025.1 1495,2025.1 1495,2003.39 ; 1465.1,2025.1 1465.1,2034.9 1510.9,2034.9 1510.9,2019.3 1495,2003.39 ; 1465.1,2025.1 1465.1,1994.9 C3.1@1475,1985 C3.1@1485,1985 ; C3.1@1485,1985 1495,1985 ; C3.1@1485,1985 1495,1975 ; 1495,1975 1495,1985 ; 1495,1985 1495,2003.39
  MidLayer2 w10: 1676,2480 ccw(c1620,2480) 1676,2480
  Bottom Layer w10: JP7.1@1641.62,131.62 R24.1@1641.62,212 ; R18.1@2102,596.38 2131,596.38 2131,720.24 R19.3@2135.38,724.62 ; R8.1@2168.62,213 v1(2197,213) 2224.38,213 R3.1@2225.38,212
  other v1: 1503,2023
BAT: C7.1 C18.1 C19.1 C20.1 J4.2 JP4.3 pad.6 TP5.1 U1.13 U1.14 | length 6337.6
  Top Layer w10: U1.14@1515.21,1713 1515.21,1675 1516.21,1675 ; U1.14@1527.84,1715 1550,1715 1555,1710 ; 1550,1710 1555,1710 ; 1558,1710 1555,1710 ; C7.1@1627,1661.53 C7.1@1627,1675 ; 1688.02,1675.13 1651.98,1675.13 1651.85,1675 C7.1@1627,1675 ; 1948,1515 2715,1515 2795,1595 2905,1595 2905,1710 ; 1958,1515 1837,1515 1723.15,1628.85 ; 2670,1690 2121,1690 ; 1516.21,1675 1518,1673.21 1518,1647 1525,1640 1712,1640 ; 1516.21,1675 C7.1@1627,1675 ; 1555,1710 1577.72,1710 1597.72,1690 1627,1690 ; C7.1@1627,1675 1627,1690 ; 1627,1690 2121,1690 ; 1712,1640 1723.15,1628.85 ; 1712,1640 1723.15,1640 1723.15,1628.85 ; 2121,1690 2141,1710 ; 2141,1710 2166,1735 2880,1735 2905,1710 ; 2141,1710 2905,1710 ; 2305,1600 ccw(c2250,1600) 2305,1600
  MidLayer2 w10: v1(1570,1700) 2150,1700 TP5.1@2250,1600 ; J4.2@2846,1675 2940,1581 2940,1170 JP4.3@2870,1100
D+/PSEL: JP1.2 JP5.2 S2.3 TP11.1 U1.2 U3.1 | length 2490.7
  Top Layer w10: JP5.2@270,1300 325,1245 420,1245 525,1350 525,1555 JP1.2@570,1600 674,1600 719,1645 1189,1645 1317.53,1773.53 U1.2@1366,1773.53 ; JP5.2@270,1309 332.32,1371.32 S2.3@332.32,1383.86 ; 520,1345 587,1345 615,1317 615,1272 565,1222 565,795 TP11.1@660,700
  Bottom Layer w10: U3.1@146.53,1338.28 146.53,1322.47 169,1300 JP5.2@270,1300
D-: JP2.1 JP5.1 S2.4 U3.2 | length 989.2
  Top Layer w10: JP5.1@370,1300 370,1382.17 S2.4@371.68,1383.86 371.68,1479.68 542,1650 670,1650 720,1700 JP2.1@770,1700
  Bottom Layer w10: U3.2@126.84,1338.28 126.84,1306.16 183,1250 320,1250 JP5.1@370,1300
D-/PG: JP2.2 TP10.1 U1.3 | length 1405.3
  Top Layer w10: TP10.1@660,900 720,960 720,1550 JP2.2@770,1600 1173,1600 1326.84,1753.84 U1.3@1366,1753.84
DSEL: JP3.3 R20.2 TP9.1 U3.9 | length 989.8
  Top Layer w10: 155,1353 v1(237,1353) ; v1@158,1429 153,1424 153,1335 273,1215 434,1215 518,1299 JP3.3@570,1299
  MidLayer2 w10: JP3.3@570,1299 570,1190 TP9.1@660,1100
  Bottom Layer w10: U3.9@146.53,1386 146.53,1414.53 v1(155,1423) ; R20.2@208,1342.38 226.38,1342.38 v1(237,1353)
ID: J5.4 J6.4 | length 725.2
  Top Layer w10: J6.4@162.61,1086.41 164.35,1084.68 222.68,1084.68 240,1102 240,1216 127,1329 127,1440 205.17,1518.17 205.17,1615.83 194.59,1626.41 J5.4@162.61,1626.41
ILIM: R1.2 TP19.1 U1.10 | length 1783.6
  Top Layer w10: U1.10@1455.84,1664 1455.84,1603.16 1485,1574 1485,618 1538,565 2013.28,565 TP19.1@2064.14,514.14 ; TP19.1@2042,524 TP19.1@2050,524
  Bottom Layer w10: TP19.1@2051,501 R1.2@2051,596.38
INT: R5.2 TP15.1 U1.7 | length 1416.1
  Top Layer w10: TP15.1@1260,501 1347,501 1395,549 U1.7@1395,1675
  Bottom Layer w10: R5.2@1188,606.38 1188,573 TP15.1@1260,501
NetC4_1: C4.1 D2.2 D5.1 L1.1 L2.1 pad.0@1620,2480 R17.2 U1.19 U1.20 | length 2597
  Top Layer w10: pad.0@1615,2480 1615,2225 ; pad.0@1625,2447 1625,2225 ; L1.1@1667.78,1985 1667.78,2006.22 1610,2064 1610,2094 1611,2095 1725,2095 ; 1615,2225 1600,2225 1600,1966.85 1584.15,1951 1555,1951 1555,1907.72 1512.28,1865 1494,1865 1475.53,1846.53 U1.20@1475.53,1824 1475.53,1814.47 1477,1813 1499,1813 1503,1817 1535,1817 1583,1865 1725,1865 1725,2095 ; 1615,2225 1625,2225 ; 1625,2225 1725,2225 1725,2095
  Bottom Layer w10: D5.1@1565,1915 1565,1951.72 ; 1565,1970 1565,1951.72 ; 1565,1951.72 1553.28,1940 1515,1940 1515,1932.72 1503.28,1921 1470,1921 1470,1895 1510,1895 1530,1875 1582,1875 1622,1915 1622,2035 1573.46,2035 1573.46,1984.17 1565,1975.72 1565,1951.72
  other v1: 1605,1933 1606,1960
NetC4_2: C4.2 D1.1 R13.2 | length 518.9
  Top Layer w10: R13.2@1515,1972 R13.2@1515,1974.62 ; R13.2@1516,1971 1575.87,1971 1580,1975.13 1580,2034 1579,2035 1531.1,2035 1531,2034.9 1531,2011.11 1515,1995.11 R13.2@1515,1974.62 ; R13.2@1524,1983.62 R13.2@1515,1974.62
  Bottom Layer w10: v1@1535,2025 1535,2002 1518,1985 1515,1985 ; 1515,1985 1515,1994 1531,2010 1531,2035 1553.46,2035 1553.46,1992.46 1545,1984 1545,1960 1515,1960 1515,1985
  other v1: 1543,2023
NetC21_1: C21.1 R17.1 | length 319.5
  Bottom Layer w10: R17.1@1660.53,2008 1660.53,2013.47 R17.1@1642,2032 ; R17.1@1642,2032 1642,2035 1735,2035 1735,2005 1703,2005 1690,1992 1690,1980 1643,1980 1642,1981 R17.1@1642,2032
NetC22_1: C22.1 U2.4 | length 363.8
  Bottom Layer w10: C22.1@276.38,1378 273.38,1381 248.6,1381 ; 248.6,1381 264.6,1365 292,1365 292,1388.72 291.72,1389 254,1389 245,1398 245,1460 206.1,1460 206.1,1434.18 215.28,1425 228.28,1425 240,1413.28 240,1381 248.6,1381
NetC23_1: C23.1 R10.2 R16.2 U2.1 | length 657.5
  Bottom Layer w10: R16.2@258,1657.38 314.38,1657.38 315,1656.76 ; 350,1515 297,1515 297,1553 275,1575 275,1626 266,1635 245,1635 245,1671 315,1671 315,1656.76 ; 350,1517 364.85,1502.15 364.85,1495 395,1495 395,1525 361,1525 315,1571 315,1656.76
NetD3_1: D3.1 R21.1 | length 102.3
  Top Layer w10: v1(1015,717) D3.1@1015,755.47
  Bottom Layer w10: R21.1@1014,653.62 1014,716 v1(1015,717)
NetD4_1: D4.1 R22.1 | length 177.9
  Top Layer w10: v1(886,717) D4.1@886,753.47
  Bottom Layer w10: v1(886,717) 964,717 R22.1@964,653.62
NetJ5_2: J5.2 S2.1 U3.7 | length 637.4
  Top Layer w10: v1@119.41,1677.59 J5.2@162.61,1677.59 372,1677.59 372,1619.01 S2.1@370.41,1617.42
  Bottom Layer w10: U3.7@107,1383 107,1566 148,1607 148,1649 v1(119,1678)
NetJ5_3: J5.3 S2.2 U3.8 | length 504.7
  Top Layer w10: J5.3@162.61,1652 330,1652 332.32,1649.68 S2.2@332.32,1616.14
  Bottom Layer w10: U3.8@127,1383 127,1555 215,1643 v1(215,1647)
NetJ6_2: J6.2 U3.4 | length 257.1
  Top Layer w10: v1(119,1138) 119.41,1137.59 J6.2@162.61,1137.59
  Bottom Layer w10: U3.4@87.47,1338.28 87.47,1169.53 v1(119,1138)
NetJ6_3: J6.3 U3.3 | length 323.2
  Top Layer w10: J6.3@162.61,1112 v1@207,1112
  Bottom Layer w10: U3.3@107.16,1338.28 107.16,1192.84 188,1112 v1@207,1112
  other v1: 207,1113
NetJ7_2: J7.2 R9.1 | length 1281.5
  Bottom Layer w10: J7.2@532,222 475,165 475,73 483,65 1392,65 1492.38,165.38 R9.1@1492.38,212
NetJ7_9: J7.9 R11.2 | length 352.4
  Bottom Layer w10: R11.2@860,306.38 809.38,306.38 782,279 782,197 807,172 859,172 909,122 J7.9@932,122
NetJ7_10: J7.10 R12.1 | length 212.2
  Bottom Layer w10: J7.10@932,222 932,306 932.38,306.38 R12.1@1060,306.38
NetJP1_3: JP1.3 R4.1 | length 76.4
  Bottom Layer w10: R4.1@570,1423.62 JP1.3@570,1500
NetJP3_2: JP3.2 U1.24 | length 1409.2
  Top Layer w10: U1.24@1396.79,1824 1396.79,1834.21 1384,1847 ; 1384,1847 1369.1,1861.9 1363.9,1861.9 1363,1861 v1(1363,1854) 1370,1847 1384,1847
  MidLayer2 w10: JP3.2@655,1314 664,1305 720,1361 720,1857 728,1865 1154,1865 1180,1839 1251.4,1839 1308.4,1782 1331.6,1782 1334.6,1785 1335,1785 1363,1813 v1(1363,1854)
NetJP9_1: JP9.1 R2.2 | length 82.2
  Bottom Layer w10: JP9.1@1930,130 1930.38,130.38 R2.2@1930.38,212
NetJP10_2: JP10.2 R8.2 | length 81.6
  Bottom Layer w10: JP10.2@2120.38,130.38 R8.2@2120.38,212
NetR1_1: R1.1 R18.2 R19.1 | length 258.2
  Bottom Layer w10: R19.1@1930,730 1930,644 1930.38,643.62 R1.1@2051,643.62 R18.2@2102,643.62
NetR10_1: R10.1 U2.3 | length 287
  Bottom Layer w10: R10.1@381,1462.38 381,1473 R10.1@383,1475 ; R10.1@383,1475 365,1475 365,1468 354,1457 295,1457 295,1435 395,1435 395,1475 R10.1@383,1475
NetR13_1: R13.1 U1.21 | length 267.2
  Top Layer w10: U1.21@1455.84,1824 1455.84,1856.84 1515,1916 1515,1951 1535,1951 1535,1918 1502,1885 1486,1885
NetR23_1: R23.1 S1.1 | length 221.2
  Top Layer w10: R23.1@2602,547.62 2740.62,547.62 2740.62,629.33 S1.1@2740,629.95
OTG: JP6.2 R6.2 TP16.1 U1.8 | length 1906.1
  Top Layer w10: JP6.2@1250,130 1460,340 TP16.1@1460,500 TP16.1@1445,515 ; U1.8@1416.47,1664 1416.47,1576.53 1425,1568 1425,535 TP16.1@1445,515 ; TP16.1@1450,520 TP16.1@1445,515
  Bottom Layer w10: R6.2@1244,606.38 1350.38,500 TP16.1@1460,500
PG: D4.2 JP2.3 JP3.1 | length 732.1
  Top Layer w10: JP2.3@770,1500 JP3.1@770,1299 885,1184 D4.2@885,815.53
PGND: C1.2 C2.2 C5.2 C6.2 C7.2 C8.2 C9.2 C10.2 C11.2 C12.2 C13.2 C14.2 C15.2 C16.2 C17.2 C18.2 C19.2 C20.2 C21.2 C22.2 C23.2 C24.2 D5.2 J1.2 J2.1 J3.1 J4.1 J5.5 J5.6 J5.7 J5.8 J5.9 J5.10 J5.11 J6.5 J6.6 J6.7 J6.8 J6.9 J6.10 J6.11 J7.6 J8.1 NT1.1 pad.0@154,2075 pad.3 pad.5 pad.7 S2.M1 S2.M2 S2.M3 S2.M4 TP6.1 TP7.1 U1.17 U1.18 U1.25 U2.2 U3.5 U3.6 | length 25085.8
  Top Layer w10: 25,915 25,2870 90,2870 130,2910 130,2975 2870,2975 2870,2910 2910,2870 2975,2870 2975,1285 1565,1285 1565,1595 1555,1605 1555,1620 1703,1620 1828,1495 2723.28,1495 2803.28,1575 2913.28,1575 2925,1586.72 2925,1718.28 2888.28,1755 2655,1755 2655,1982.72 2797.28,2125 2882,2125 2935,2178 2935,2342.28 2922.28,2355 2541.72,2355 2301.72,2115 2029.28,2115 1899.28,2245 1645,2245 1645,2273 ; J5.11@148.64,1748.46 148.64,1870.64 254.64,1870.64 ; J6.6@148.83,1015.54 157,1023.71 J6.6@157,1033 ; J5.5@162.61,1600.82 157,1595.2 157,1563.71 166,1572.71 J5.5@166,1596 ; J5.11@181,1740 181,1749.85 254.64,1823.49 254.64,1870.64 ; S2.M4@409.09,1415.35 v1@440.44,1384 ; TP6.1@650,2500 700,2450 v1(700,2400) ; 677.5,2416.67 ccw(c700,2400) 722.52,2416.64 ; 677.5,2417 610,2417 ; 722.52,2417 757,2417 757,2583 542,2583 542,2417 610,2417 ; C2.2@1337.47,1932 1346,1932 C2.2@1355,1941 ; U1.17@1515,1773 1515,1797 1543.28,1797 1591.28,1845 v1@1615,1845 ; U1.17@1528.53,1773 1553,1773 1565,1785 ; 1563,1780 1767,1780 C17.2@1770,1783 ; C5.2@1615,1801 v1@1615,1845 ; 1684,2273 1645,2273 ; C17.2@1771,1784 1771,1839 1765,1845 v1@1615,1845 ; 2177.39,2416.52 ccw(c2200,2400) 2222.4,2416.8 ; 2177.39,2417 2143,2417 2143,2583 2358,2583 2358,2417 2251,2417 ; v1(2200,2400) 2200,2450 TP7.1@2250,2500 ; 2222.4,2417 2251,2417 ; 2251,2351 2251,2417 ; J6.6@157,1033 157,1055.2 J6.5@162.61,1060.82 162.61,1038.61 J6.6@157,1033 ; 254.64,1870.64 254.64,2047.08 186.72,2115 76.72,2115 65,2126.72 65,2289.28 110.72,2335 610,2335 ; 610,2335 701,2335 1191,1845 1335,1845 1335,1865.6 1351.4,1882 1355,1882 C2.2@1355,1941 ; 610,2335 610,2417 ; C2.2@1355,1941 1355,2016.72 1255,2116.72 1255,2445.72 945.72,2755 864.72,2755 825,2794.72 825,2882.28 867.72,2925 1183.28,2925 1225,2883.28 1225,2807.28 1237.28,2795 1352.28,2795 1465,2682.28 1465,2054.9 1465.1,2055 1580,2055 1580,2233.28 1591.72,2245 1595,2245 1595,2431 cw(c1620,2480) 1645.01,2431.02 1645,2273
  MidLayer1 w10: 1676,2480 ccw(c1620,2480) 1676,2480
  MidLayer2 w10: v1(700,2400) 1029,2071 1255,2071 1340,1986 v1(1340,1977) ; v1(1613,1836) 1613,1842 2043,2272 2115,2272 2131,2288 2131,2331 v1(2200,2400)
  Bottom Layer w10: U2.2@317.24,1486 v1(273,1486) 277,1490 277,1504 ; C22.2@323.62,1378 323.62,1414.62 323.24,1415 ; 265,1475 265,1538 249,1554 190,1554 177.13,1541.13 177.13,1531 149,1531 149,1548.72 215.28,1615 255,1615 255,1566.72 277,1544.72 277,1504 ; 265,1475 284.72,1475 ; 265,1475 265,1414 270,1409 300,1409 312,1397 312,1364 339,1364 340,1365 340,1415 323.24,1415 ; 277,1504 286,1495 340,1495 340,1477 286.72,1477 284.72,1475 ; 284.72,1475 275,1465.28 275,1426.72 286.72,1415 323.24,1415 ; 1676,2480 ccw(c1620,2480) 1676,2480
  other v1: 60,927 123,967 55,1293 2710,1310 2780,1310 2850,1310 446,1375 692,1376 2710,1380 2780,1380 2850,1380 2710,1450 2780,1450 2850,1450 55,1467 1615,1470 1715,1470 1815,1470 1915,1470 2015,1470 2115,1470 1615,1567 1665,1567 1715,1567 1587,1607 1668,1607 1647,1836 1683,1836 1717,1836 1753,1836 2710,1850 2780,1850 2850,1850 100,1860 170,1860 240,1860 1220,1887 1303,1887 1340,1887 2710,1920 2780,1920 2850,1920 100,1930 170,1930 240,1930 1220,1977 1303,1977 2710,1990 2780,1990 2850,1990 100,2000 170,2000 240,2000 1099,2099 1199,2099 1099,2199 1199,2199 1900,2300 2000,2300 2100,2300 2200,2300 2300,2300 500,2400 600,2400 800,2400 900,2400 1000,2400 1900,2400 2000,2400 2100,2400 2300,2400 500,2500 800,2500 900,2500 1000,2500 1900,2500 2000,2500 2100,2500 2400,2500 2500,2500 2600,2500 2700,2500
  other v2: 1410,1708 1446,1708 1482,1708 1410,1744 1446,1744 1482,1744 1410,1780 1446,1780 1482,1780
PMID: C2.1 C9.1 C10.1 C11.1 C12.1 C13.1 D2.1 J2.2 pad.2 TP2.1 U1.23 | length 5114.2
  Top Layer w10: 1275,2524 1275,2454 ; C9.1@1388.62,2002 1388.62,2011.38 1375,2025 ; U1.23@1416,1835 1416,1844 ; 1416.16,1844.33 1396.53,1863.96 ; U1.23@1416.47,1824 1416.47,1903.53 ; v1@1416.47,1973.53 v1@1416.47,1965.47 ; 1157,2905 1175,2905 1205,2875 1205,2799 1229,2775 1344,2775 1445,2674 1445,1994 ; 1157,2905 876,2905 845,2874 845,2803 873,2775 954,2775 1275,2454 ; 1157,2905 1174,2888 1174,2793 1375,2592 1375,2354 ; 1275,2454 1375,2354 ; 1275,2454 1275,2125 1375,2025 ; 1375,2025 1375,2354 ; 1375,2025 1375,1885.49 1396.53,1863.96 ; 1396.53,1863.96 C2.1@1396.53,1923.47 ; C2.1@1396.53,1923.47 C2.1@1396.53,1932 1396.53,1945.53 v1@1416.47,1965.47 ; C2.1@1396.53,1923.47 1416.47,1903.53 ; 1416.47,1903.53 v1@1416.47,1965.47 ; v1@1416.47,1965.47 1430,1979 ; 1430,1979 1445,1994 ; 1430,1979 1445,1979 1445,1994
  Bottom Layer w10: C10.1@1396.53,1932 C10.1@1396.53,1933.47 ; C10.1@1397.03,1932 C10.1@1418,1932 ; C10.1@1418,1943 C10.1@1418,1937.72 ; 1425,2070 1425,2066 ; 1375,1904 1375,2155 1425,2155 1425,2066 ; 1375,1904 1418,1904 C10.1@1418,1932 ; 1375,1904 1375,1895 1453,1895 1453,1921 1434.72,1921 1423.72,1932 ; C10.1@1418,1932 1423.72,1932 ; C10.1@1418,1932 C10.1@1418,1937.72 ; C10.1@1418,1937.72 1418,1963 1425,1970 1425,2066 ; C10.1@1418,1937.72 1423.72,1932
  other v1: 1383,1977 1413,1977 1400,2042 1400,2106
